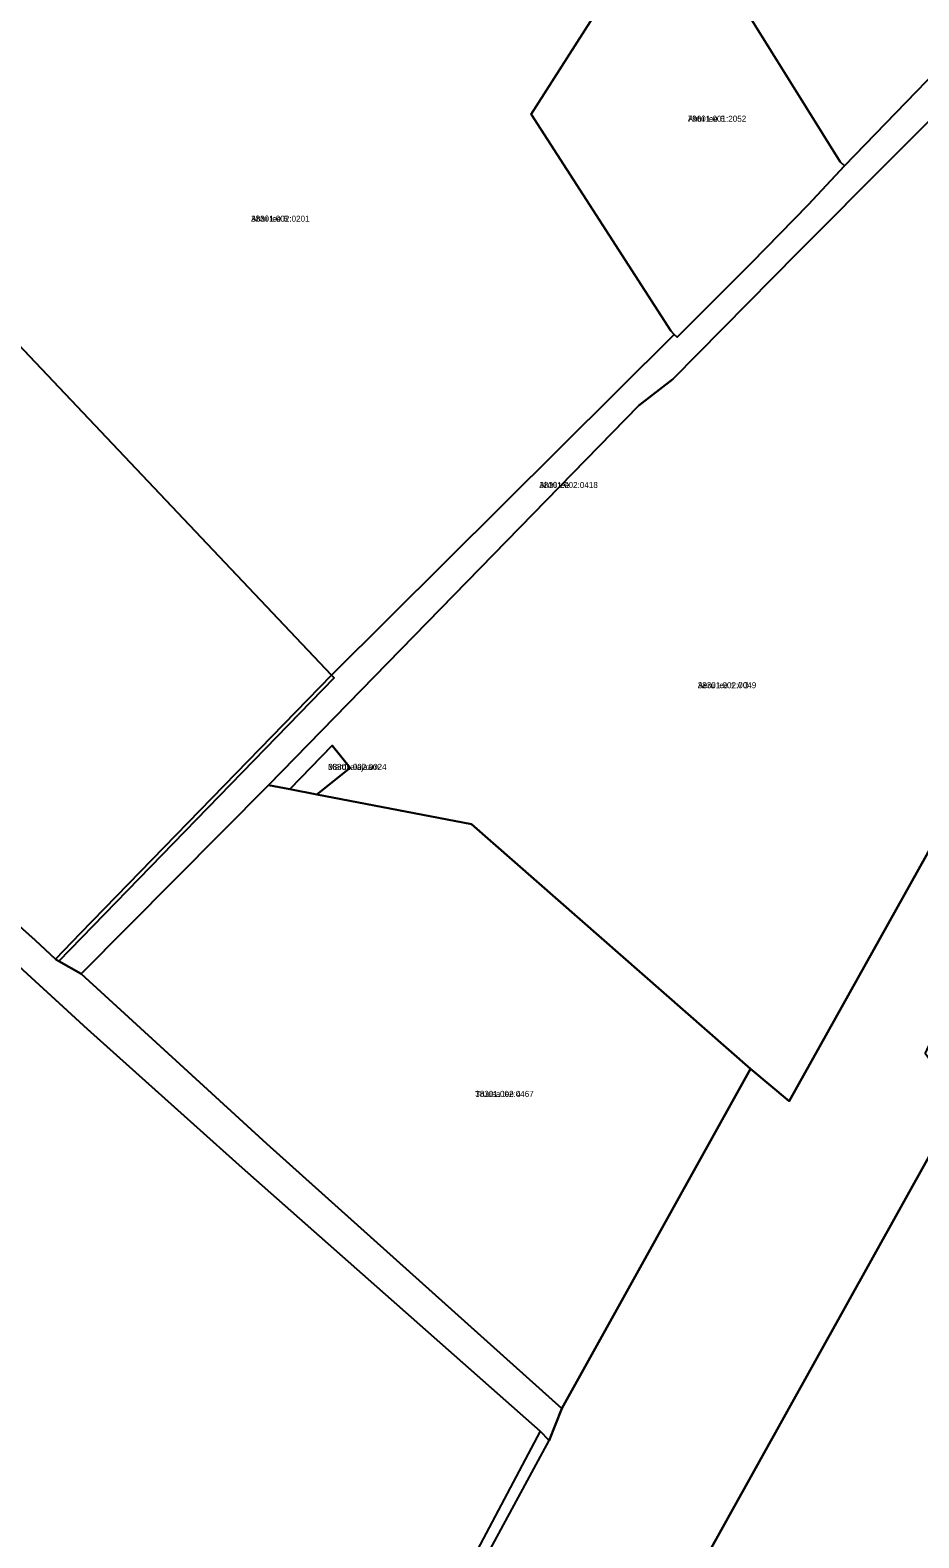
# Model space of a CAD drawing. Extents: x 625111 to 706696, y 6474150 to 6504223.
# Drawn here: x 638557.6 to 638778, y 6485129 to 6485502.8 of the extents above; entities that cross this region are included whole.
import ezdxf

# ---------------------------------------------------------------- set-up
doc = ezdxf.new("R2010")
doc.units = 0
for name, color, linetype in [('L_AADRESS', 7, 'Continuous'), ('PIIR', 7, 'Continuous'), ('TUNNUS', 7, 'Continuous')]:
    doc.layers.add(name, color=color, linetype=linetype)

msp = doc.modelspace()

# ---------------------------------------------------------------- linework, layer by layer
at = {"layer": 'PIIR'}
for points in [[(638604.54, 6485525.38), (638618.75, 6485536.74), (638649.52, 6485555.32), (638667.66, 6485567.71), (638669, 6485565.85), (638704.07, 6485516.87), (638681.79, 6485482), (638716.44, 6485428.23), (638717.29, 6485427.39), (638632.31, 6485342.92), (638525.12, 6485455.99), (638449.86, 6485377.79), (638373.68, 6485447.27), (638414.83, 6485545.54), (638414.96, 6485547.19), (638433.74, 6485545.86), (638507.36, 6485540.61), (638542.8, 6485536.4), (638555.52, 6485535.25), (638562.51, 6485532.83), (638569.88, 6485528.93), (638573.42, 6485527.26), (638587.08, 6485525.7), (638600.98, 6485524.83)], [(638742.82, 6485568.79), (638781.99, 6485513.33), (638795.27, 6485512.53), (638796.61, 6485512.41), (638798.39, 6485509.3), (638797.64, 6485508.52), (638759.55, 6485469.21), (638758.48, 6485470.2), (638720.26, 6485531.5)], [(638709.69, 6485521.96), (638720.26, 6485531.5), (638758.48, 6485470.2), (638759.55, 6485469.21), (638750.53, 6485459.52), (638736.44, 6485445.14), (638718, 6485426.69), (638717.29, 6485427.39), (638716.44, 6485428.23), (638681.79, 6485482), (638704.07, 6485516.87)], [(638616.72, 6485315.58), (638570.26, 6485268.85), (638564.72, 6485271.94), (638633.01, 6485342.2), (638632.31, 6485342.92), (638717.29, 6485427.39), (638718, 6485426.69), (638736.44, 6485445.14), (638750.53, 6485459.52), (638759.55, 6485469.21), (638797.64, 6485508.52), (638800.82, 6485503.13), (638803.01, 6485499.59), (638801.49, 6485499.35), (638798.84, 6485498.32), (638795.69, 6485495.51), (638747.94, 6485447.72), (638716.99, 6485416.28), (638708.55, 6485409.73)], [(638525.12, 6485455.99), (638632.31, 6485342.92), (638569.97, 6485278.8), (638563.88, 6485272.47), (638558.82, 6485277.17), (638532.71, 6485300.52), (638501.69, 6485328.06), (638449.86, 6485377.79)], [(638433.73, 6485382.86), (638370.86, 6485440.54), (638373.68, 6485447.27), (638427.65, 6485398.03), (638449.86, 6485377.79), (638501.69, 6485328.06), (638532.71, 6485300.52), (638558.82, 6485277.17), (638563.88, 6485272.47), (638564.72, 6485271.94), (638570.26, 6485268.85), (638616.23, 6485226.72), (638689.4, 6485161.09), (638686.3, 6485153.17), (638684.02, 6485155.44), (638610.16, 6485220.71), (638571.77, 6485255.1), (638478.74, 6485340.45)], [(638636.95, 6485319.9), (638628.66, 6485313.34), (638621.97, 6485314.63), (638632.45, 6485325.47)], [(638616.72, 6485315.58), (638621.97, 6485314.63), (638628.66, 6485313.34), (638667.04, 6485305.94), (638736.24, 6485245.3), (638689.4, 6485161.09), (638616.23, 6485226.72), (638570.26, 6485268.85)], [(638931.59, 6485002.42), (638870.49, 6484835.17), (638723.26, 6485120.65), (638788.19, 6485237.4), (638838.72, 6485163.5), (638933.57, 6485024.77), (638938.01, 6485026.87), (639015.85, 6485066.04), (639017.1, 6485021.15)]]:
    msp.add_lwpolyline(points, close=True, dxfattribs=at)
for points in [[(638802.18, 6485544.13), (638826.7, 6485502.4), (638836.81, 6485484.18), (638841.03, 6485475.01), (638845.25, 6485463.97), (638849.42, 6485450.41), (638852.13, 6485435.31), (638853.33, 6485415.33), (638852.48, 6485411.67), (638844.35, 6485376.71), (638833.13, 6485349.78), (638810.23, 6485304.88), (638804.94, 6485295.29), (638799.77, 6485287.11), (638783.12, 6485256.93), (638779.54, 6485249.16), (638788.19, 6485237.4), (638723.26, 6485120.65), (638562.67, 6484825.18), (638546.32, 6484825.91)], [(638528.72, 6484862.32), (638686.3, 6485153.17), (638689.4, 6485161.09), (638736.24, 6485245.3), (638745.8, 6485237.26), (638787.4, 6485311.71), (638787.91, 6485312.41), (638789.67, 6485315.31), (638809.97, 6485353.32), (638811.86, 6485356.95), (638818.71, 6485372.53), (638822.76, 6485383.22), (638825.69, 6485398.82), (638828.12, 6485408.53), (638829.36, 6485422.49), (638829.6, 6485431.48), (638829.02, 6485441.3), (638826.69, 6485451.91), (638823.64, 6485460.32), (638818.36, 6485471.86), (638805.53, 6485496.41), (638803.01, 6485499.59), (638800.82, 6485503.13)], [(638787.4, 6485311.71), (638745.8, 6485237.26), (638736.24, 6485245.3), (638667.04, 6485305.94), (638628.66, 6485313.34), (638636.95, 6485319.9), (638632.45, 6485325.47), (638621.97, 6485314.63), (638616.72, 6485315.58), (638708.55, 6485409.73), (638716.99, 6485416.28), (638747.94, 6485447.72), (638795.69, 6485495.51)], [(638478.74, 6485340.45), (638571.77, 6485255.1), (638610.16, 6485220.71), (638684.02, 6485155.44), (638528.72, 6484862.32)]]:
    msp.add_lwpolyline(points, dxfattribs=at)

# ---------------------------------------------------------------- texts
at = {"layer": 'L_AADRESS'}
for s, p in [('Ahtri tee 6', (638720.67, 6485480.1)), ('Ahtri tee 8', (638612.37, 6485455.32)), ('Ahtri tee', (638683.86, 6485389.29)), ('Aeru tee 1 // 3', (638723.16, 6485339.65)), ('Märdi alajaam', (638631.46, 6485319.4)), ('Truusa tee 4', (638667.96, 6485238.33))]:
    msp.add_text(s, height=1.5, dxfattribs=at).set_placement(p)
at = {"layer": 'TUNNUS'}
for s, p in [('79601:001:2052', (638720.67, 6485480.1)), ('38301:002:0201', (638612.37, 6485455.32)), ('38301:002:0418', (638683.86, 6485389.29)), ('38301:002:0049', (638723.16, 6485339.65)), ('38301:002:0024', (638631.46, 6485319.4)), ('38301:002:0467', (638667.96, 6485238.33))]:
    msp.add_text(s, height=1.5, dxfattribs=at).set_placement(p)

doc.saveas('drawing.dxf')
